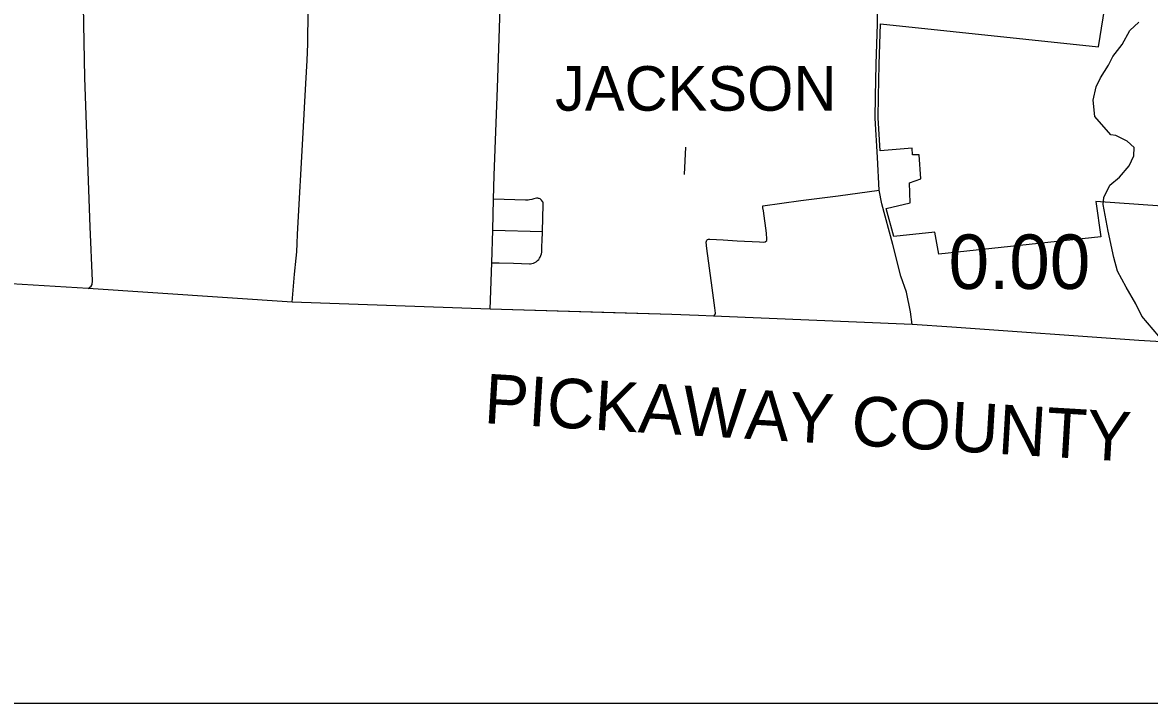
# Model space of a CAD drawing. Extents: x 1659811 to 1934326, y 644115 to 934867.
# Drawn here: x 1801590 to 1824362, y 650175 to 663921 of the extents above; entities that cross this region are included whole.
import ezdxf

# ---------------------------------------------------------------- set-up
doc = ezdxf.new("R2010")
doc.units = 0
for name, color, linetype in [('Default', 7, 'Continuous'), ('GM_X_Adjacent_County_Text', 7, 'Continuous'), ('GM_X_Corporation', 7, 'Continuous'), ('GM_X_County', 7, 'Continuous'), ('GM_X_County_Road', 7, 'Continuous'), ('GM_X_State_Route', 7, 'Continuous'), ('GM_X_Township', 7, 'Continuous'), ('GM_X_Township_Road', 7, 'Continuous'), ('GM_X_Township_Text', 7, 'Continuous'), ('SC_Scratch1', 7, 'Continuous')]:
    doc.layers.add(name, color=color, linetype=linetype)

msp = doc.modelspace()

# ---------------------------------------------------------------- linework, layer by layer
at = {"layer": 'GM_X_Corporation'}
msp.add_lwpolyline([(1826346, 660092), (1823279, 660307), (1823376, 659594), (1820105, 659247), (1820026, 659688), (1819193, 659600), (1819043, 660170), (1819529, 660281), (1819511, 660687), (1819745, 660769), (1819709, 661248), (1819573, 661248), (1819570, 661382), (1818918, 661330), (1818878, 661995), (1818887, 662426), (1818900, 663077), (1818925, 663896), (1823332, 663432), (1823518, 664608)], dxfattribs=at)
at = {"layer": 'GM_X_County'}
msp.add_lwpolyline([(1824608, 657476), (1824149, 657505), (1820365, 657774), (1819565, 657827), (1815551, 657995), (1815251, 658006), (1814713, 658027), (1811039, 658133), (1807036, 658278), (1802918, 658549), (1799575, 658756), (1799409, 658764), (1794213, 659039), (1792928, 659077), (1789408, 659196), (1786100, 659304), (1784956, 659328), (1781576, 659434)], dxfattribs=at)
at = {"layer": 'GM_X_County_Road'}
msp.add_lwpolyline([(1807036, 658278), (1807084, 658842), (1807119, 659163), (1807132, 659294), (1807140, 659461), (1807143, 659649), (1807258, 661693), (1807288, 662202), (1807315, 662693), (1807343, 663154), (1807353, 663488), (1807361, 664158), (1807373, 665125), (1807380, 665621)], dxfattribs=at)
at = {"layer": 'GM_X_State_Route'}
for points in [[(1818865, 663903), (1818869, 664029), (1818882, 664535)], [(1819565, 657827), (1819530, 658083), (1819453, 658477), (1819341, 658803), (1819173, 659438), (1818957, 660262), (1818902, 660536), (1818866, 661195), (1818818, 661994), (1818827, 662427), (1818840, 663079), (1818865, 663897), (1818865, 663903)]]:
    msp.add_lwpolyline(points, dxfattribs=at)
at = {"layer": 'GM_X_Township'}
msp.add_lwpolyline([(1824553, 657587), (1824209, 657995), (1824084, 658243), (1823890, 658579), (1823715, 658902), (1823642, 659178), (1823529, 659708), (1823424, 660245), (1823439, 660389), (1823563, 660639), (1823758, 660802), (1823951, 661031), (1824046, 661230), (1824053, 661398), (1823908, 661523), (1823682, 661644), (1823580, 661654), (1823258, 662024), (1823223, 662356), (1823282, 662621), (1823374, 662802), (1823537, 663064), (1823620, 663238), (1823813, 663475), (1823965, 663763), (1824144, 663928)], dxfattribs=at)
at = {"layer": 'GM_X_Township_Road'}
for points in [[(1802918, 658549), (1802980, 658597), (1802995, 658634), (1803006, 658708), (1802958, 659796), (1802900, 661294), (1802846, 662815), (1802821, 664254), (1802796, 665173), (1802793, 665313), (1802839, 665876)], [(1811039, 658133), (1811072, 659073), (1811090, 659728), (1811110, 660352), (1811119, 660831), (1811186, 662602), (1811227, 663802), (1811276, 665382), (1811291, 665875)], [(1814965, 660853), (1814995, 661407)], [(1815551, 657995), (1815575, 658012), (1815590, 658037), (1815593, 658057), (1815581, 658160), (1815528, 658564), (1815420, 659358), (1815404, 659486), (1815408, 659507), (1815420, 659527), (1815433, 659540), (1815450, 659546), (1815480, 659550), (1815748, 659532), (1816032, 659517), (1816480, 659491), (1816558, 659488), (1816595, 659497), (1816630, 659521), (1816631, 659549), (1816626, 659670), (1816562, 660118), (1816549, 660179), (1816546, 660222), (1817320, 660326), (1818070, 660426), (1818902, 660536)], [(1811072, 659073), (1811223, 659069), (1811508, 659060), (1811835, 659050), (1811856, 659050), (1811881, 659054), (1811913, 659062), (1811942, 659075), (1811971, 659093), (1811999, 659117), (1812021, 659140), (1812038, 659162), (1812052, 659187), (1812066, 659220), (1812076, 659255), (1812081, 659284), (1812085, 659415), (1812089, 659509), (1812095, 659700), (1812111, 660245), (1812107, 660281), (1812101, 660300), (1812091, 660318), (1812078, 660333), (1812064, 660347), (1812047, 660359), (1812032, 660366), (1812017, 660371), (1812000, 660373), (1811976, 660373), (1811951, 660370), (1811922, 660362), (1811883, 660350), (1811832, 660340), (1811807, 660336), (1811783, 660336), (1811752, 660335), (1811110, 660352)], [(1811090, 659728), (1812095, 659700)], [(1813295, 658068), (1811039, 658133)], [(1815551, 657995), (1815251, 658006), (1814713, 658027), (1813295, 658068)]]:
    msp.add_lwpolyline(points, dxfattribs=at)
at = {"layer": 'SC_Scratch1'}
msp.add_lwpolyline([(1730291, 784675), (1926541, 784675), (1926541, 650175), (1730291, 650175)], close=True, dxfattribs=at)

# ---------------------------------------------------------------- texts
at = {"layer": 'Default'}
msp.add_text('0.00', height=1100, dxfattribs=at).set_placement((1820303, 658542))
at = {"layer": 'GM_X_Adjacent_County_Text'}
msp.add_text('PICKAWAY COUNTY', height=1000, rotation=356.5821, dxfattribs=at).set_placement((1810900, 655835))
at = {"layer": 'GM_X_Township_Text'}
msp.add_text('JACKSON', height=900, rotation=0, dxfattribs=at).set_placement((1812351, 662141))

doc.saveas('drawing.dxf')
